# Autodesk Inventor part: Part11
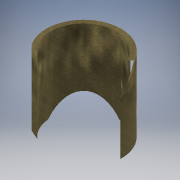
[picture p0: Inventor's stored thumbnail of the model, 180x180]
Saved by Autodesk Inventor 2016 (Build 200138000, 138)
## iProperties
Created: 2020-04
Part Number: Part11
Material: Generic
Document SubType Name: Modeling
Designer: merlin
Density: 1 g/cm^3
Appearance: Foil Gold
Author: merlin
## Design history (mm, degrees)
sketch "Sketch1"
  geometry: L1 (-433.222, 108.891)-(-426.074, 101.415); L2 (-433.222, 108.891)-(-417.048, 101.909); A1 r 63.52 centre (-469.9, 66.675) between (-533.4, 68.263) and (-417.048, 101.909); A2 r 55.924 centre (-469.9, 66.675) between (-525.462, 60.325) and (-426.074, 101.415); A3 r 9.371 centre (-524.032, 68.028) between (-533.4, 68.263) and (-525.258, 58.738); 1 further point
  constraints: 9 point on circle, 4 end point, 3 centre point, 1 coincident, 1 tangent
extrude "Extrusion1" new body sketch "Sketch1" distance "d0" = 127; taper "d1" = 0 deg
body "Solid1"
